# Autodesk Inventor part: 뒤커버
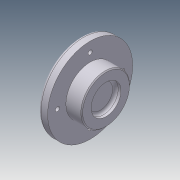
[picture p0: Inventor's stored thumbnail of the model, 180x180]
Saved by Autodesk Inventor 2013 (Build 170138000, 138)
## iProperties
Company: 한국ATC센터
Created: 2014-11
Part Number: 뒤커버
Document SubType Name: Modeling
Designer: KYOUNG IL JANG
Density: 2.71 g/cm^3
Material: 알루미늄-6061
Mass: 280.898 g
Surface Area: 198.677 cm^2
Volume: 103.653 cm^3
Author: KYOUNG IL JANG
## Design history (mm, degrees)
sketch "스케치1"
  geometry: L1 (-13.5, 0)-(13.5, 0); L2 (-13.5, 0)-(-13.5, 45.5); L3 (-13.5, 45.5)-(-3.5, 45.5); L4 (-3.5, 45.5)-(-3.5, 26); L5 (-3.5, 26)-(13.5, 26); L6 (13.5, 26)-(13.5, 0); 2 further points
  constraints: 12 end point, 3 parallel, 2 perpendicular, 1 coincident, 1 horizontal, 1 midpoint
  dimensions: "d0" = 27 distance of L1.start L1.end; "d1" = 91 diameter of L3 L1; "d2" = 52 diameter of L5 L1; "d3" = 10 distance of L2.end L3.end
revolve "회전1" sketch "스케치1" stored, may be unused: angle "d4" = 90 deg
sketch "스케치2"
  geometry: 2 further points
  constraints: 1 vertical alignment
  dimensions: "d14" = 35 distance of point (0, 0) point (0, 35)
hole "구멍2" sketch "스케치2" at (0, 35) diameter "d15" = 4.5; stored, may be unused: countersink angle "d19" = 90 deg, drill point angle "d21" = 118 deg; dims "d16" = 6, "d17" = 8, "d18" = 4.4, "d20" = 8
fillet "모깎기1" dims "d29" = 3
chamfer "모따기2" distance "d30" = 1; stored, may be unused: second distance "d31" = 2, angle "d32" = 30 deg
sketch "스케치3"
  geometry: L1 (-22.444, 6.652)-(-10, 14.967); L2 (-22.444, -6.652)-(-10, -14.967); L3 (10, -14.967)-(22.444, -6.652); L4 (22.444, 6.652)-(10, 14.967); A1 r 18 centre (0, 0) between (-18, 0) and (18, 0); A2 r 8 centre (18, 0) between (22.444, -6.652) and (22.444, 6.652); A3 r 8 centre (-18, 0) between (-22.444, 6.652) and (-22.444, -6.652); 1 further point
  constraints: 10 point on circle, 8 end point, 6 tangent, 3 centre point, 2 horizontal alignment, 2 parallel, 1 coincident, 1 equal radius
  dimensions: "d36" = 36 diameter of A1; "d37" = 16 diameter of A2
extrude "돌출1" join sketch "스케치3" distance "d38" = 7; taper "d39" = 0 deg
hole "구멍3" diameter "d43" = 32; stored, may be unused: countersink angle "d47" = 90 deg, drill point angle "d49" = 0 deg; dims "d41" = 10, "d42" = 10, "d44" = 6, "d45" = 4, "d46" = 2, "d48" = 6
fillet "모깎기2" dims "d40" = 3
node "솔리드1"
pattern_circular "원형 패턴2" dims angle "d34" = 360 deg
